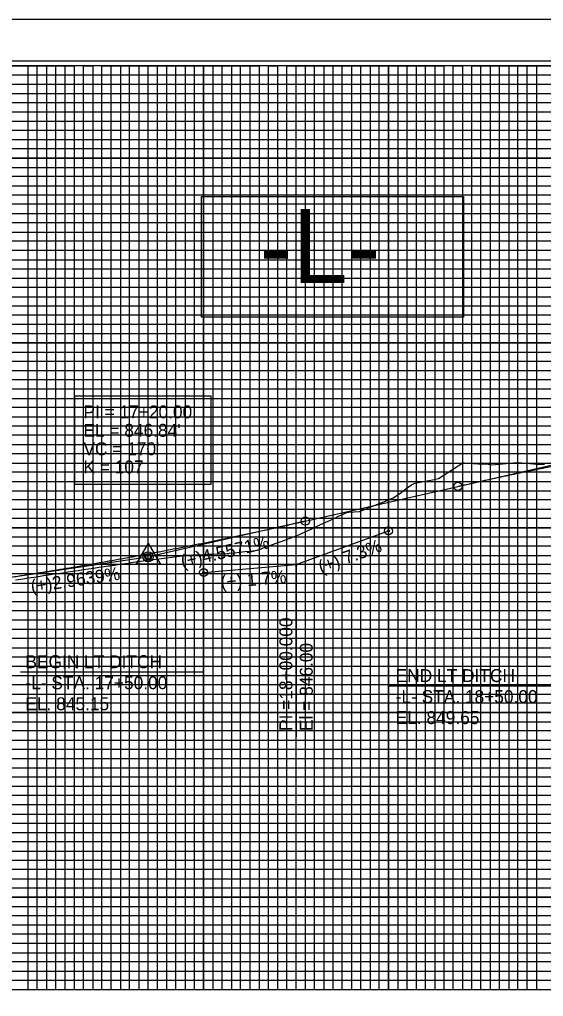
# Model space of a CAD drawing. Extents: x 570622 to 580296, y -55533 to -48575.
# Drawn here: x 571339 to 571622, y -52761 to -52232 of the extents above; entities that cross this region are included whole.
import ezdxf

# ---------------------------------------------------------------- set-up
doc = ezdxf.new("R2010")
doc.units = 0
for name, color, linetype in [('Exist Vertical Profile Ground Line', 7, 'Continuous'), ('Prop Grid Mask', 7, 'Continuous'), ('Prop PFL VPI Symbol CELL', 7, 'Continuous'), ('Prop Vertical Profile Curve Label', 7, 'Continuous'), ('Prop Vertical Profile Ditch Grade Left', 7, 'Continuous'), ('Prop Vertical Profile Ditch Grade Left Label', 7, 'Continuous'), ('Prop Vertical Profile Grade', 7, 'Continuous'), ('Prop Vertical Profile Grade Label', 7, 'Continuous'), ('Prop VPI Ditch Grade Left Label', 7, 'Continuous'), ('Prop VPI Label', 7, 'Continuous'), ('Sheet Cutting Line CELL', 7, 'Continuous'), ('Sheet Data Field CELL', 7, 'Continuous'), ('Sheet DOT Grid CELL', 7, 'Continuous'), ('Sheet Layout Profile Border Port 1', 7, 'Continuous'), ('Sheet Plot Border Inside CELL', 7, 'Continuous'), ('Sheet Plot Border Outside CELL', 7, 'Continuous'), ('Sheet Profile CELL', 7, 'Continuous'), ('Sheet Profile Grid Major CELL', 7, 'Continuous'), ('Sheet Profile Grid Middle CELL', 7, 'Continuous'), ('Sheet Profile Grid Minor CELL', 7, 'Continuous')]:
    doc.layers.add(name, color=color, linetype=linetype)

msp = doc.modelspace()

# ---------------------------------------------------------------- linework, layer by layer
at = {"layer": 'Exist Vertical Profile Ground Line'}
for points in [[(571384.91, -52528.05), (571386.95, -52527.76), (571387.73, -52527.65), (571390.54, -52527.24), (571393.36, -52526.84), (571396.18, -52526.44), (571399, -52526.04), (571399.51, -52525.96), (571401.81, -52525.61), (571404.63, -52525.18), (571407.45, -52524.76), (571407.98, -52524.68), (571410.26, -52524.4), (571413.08, -52524.05), (571415.9, -52523.71), (571417.33, -52523.54), (571418.72, -52523.36), (571421.53, -52522.99), (571423.97, -52522.67), (571424.35, -52522.62), (571427.17, -52522.22), (571428.89, -52521.98), (571429.98, -52521.93), (571432.8, -52521.79), (571435.62, -52521.67), (571438.44, -52521.55), (571441.25, -52521.44), (571444.07, -52521.33), (571446.89, -52521.24), (571449.7, -52521.15), (571450.1, -52521.14), (571452.52, -52520.88), (571455.34, -52520.59), (571458.16, -52520.3), (571460.97, -52520.02), (571463.79, -52519.75), (571466.76, -52519.47), (571469.96, -52518.48), (571470.26, -52518.33), (571470.96, -52517.96), (571472.24, -52517.51), (571475.06, -52516.5), (571477.88, -52515.47), (571480.69, -52514.44), (571483.51, -52513.39), (571486.33, -52512.33), (571489.14, -52511.25), (571490.61, -52510.69), (571491.96, -52510.06), (571494.78, -52508.74), (571497.59, -52507.4), (571500.41, -52506.06), (571501.88, -52505.35), (571503.23, -52504.75), (571506.05, -52503.48), (571508.86, -52502.2), (571511.68, -52500.9), (571514.5, -52499.59), (571516.51, -52498.65), (571517.31, -52498.61), (571520.13, -52498.47), (571522.95, -52498.22), (571525.77, -52497.12), (571528.58, -52496), (571531.4, -52494.88), (571534.22, -52493.74), (571534.68, -52493.55), (571537.03, -52492.62), (571539.85, -52491.5), (571541.25, -52490.94), (571542.67, -52489.94), (571545.49, -52487.94), (571548.3, -52485.92), (571551.12, -52483.9), (571551.8, -52483.41), (571552.83, -52483), (571553.94, -52482.79), (571556.75, -52482.23), (571559.57, -52481.66), (571562.39, -52481.08), (571565.74, -52480.38), (571578.88, -52472), (571579.51, -52471.94), (571589.38, -52472.75), (571591.66, -52472.55), (571594.6, -52473.06), (571608.31, -52471.84), (571608.71, -52471.82), (571621.35, -52472.8), (571622.98, -52472.61)], [(571337.02, -52535.3), (571339.84, -52534.87), (571342.21, -52534.51), (571342.65, -52534.44), (571345.47, -52534), (571348.29, -52533.57), (571351.11, -52533.13), (571352.05, -52532.99), (571353.92, -52532.7), (571356.74, -52532.27), (571359.56, -52531.85), (571362.37, -52531.42), (571364.6, -52531.08), (571365.19, -52530.99), (571368.01, -52530.57), (571370.83, -52530.14), (571373.64, -52529.72), (571376.46, -52529.3), (571379.28, -52528.88), (571382.09, -52528.47), (571383.66, -52528.24), (571384.91, -52528.05)]]:
    msp.add_lwpolyline(points, dxfattribs=at)
at = {"layer": 'Prop Grid Mask'}
for points in [[(571437.59, -52327.87), (571579.27, -52327.87), (571579.27, -52393.13), (571437.59, -52393.13)], [(571369.03, -52435.65), (571442.68, -52435.65), (571442.68, -52483.76), (571369.03, -52483.76)]]:
    msp.add_lwpolyline(points, close=True, dxfattribs=at)
at = {"layer": 'Prop PFL VPI Symbol CELL'}
for p, q in [((571408.68, -52515.37), (571402.23, -52526.57)), ((571408.68, -52515.37), (571415.18, -52526.57)), ((571402.23, -52526.57), (571415.18, -52526.57))]:
    msp.add_line(p, q, dxfattribs=at)
for radius in [1.75, 1.2]:
    msp.add_circle((571408.69, -52522.85), radius, dxfattribs=at)
at = {"layer": 'Prop Vertical Profile Curve Label'}
for centre in [(571576.19, -52484.69), (571493.69, -52503.49)]:
    msp.add_circle(centre, 2.25, dxfattribs=at)
at = {"layer": 'Prop Vertical Profile Ditch Grade Left'}
msp.add_lwpolyline([(571438.69, -52531.3), (571488.69, -52527.05), (571538.69, -52508.8)], dxfattribs=at)
at = {"layer": 'Prop Vertical Profile Ditch Grade Left Label'}
for p, q in [((571538.69, -52508.8), (571538.69, -52592.8)), ((571488.69, -52527.05), (571488.69, -52620.19)), ((571438.69, -52531.3), (571438.69, -52585.3)), ((571438.69, -52585.3), (571339.59, -52585.3)), ((571637.94, -52592.8), (571538.69, -52592.8))]:
    msp.add_line(p, q, dxfattribs=at)
at = {"layer": 'Prop Vertical Profile Grade'}
msp.add_line((571493.69, -52503.49), (571576.19, -52484.69), dxfattribs=at)
for points in [[(571576.19, -52484.69), (571580.69, -52483.67), (571585.19, -52482.66), (571589.69, -52481.66), (571594.19, -52480.67), (571598.69, -52479.7), (571603.19, -52478.73), (571607.69, -52477.78), (571612.19, -52476.83), (571616.69, -52475.9), (571621.19, -52474.98), (571625.69, -52474.07), (571630.19, -52473.17), (571634.69, -52472.28), (571639.19, -52471.4), (571643.69, -52470.54), (571648.19, -52469.68), (571652.69, -52468.84), (571657.19, -52468), (571661.69, -52467.18), (571666.19, -52466.37), (571670.69, -52465.56), (571675.19, -52464.77), (571679.69, -52463.99), (571684.19, -52463.22), (571688.69, -52462.47), (571693.19, -52461.72), (571697.69, -52460.98), (571702.19, -52460.26), (571706.69, -52459.54), (571711.19, -52458.84), (571715.69, -52458.15), (571720.19, -52457.47), (571724.69, -52456.8), (571729.19, -52456.14), (571733.69, -52455.49), (571738.19, -52454.85), (571742.69, -52454.22), (571747.19, -52453.61), (571751.69, -52453), (571756.19, -52452.41), (571760.69, -52451.83), (571765.19, -52451.25), (571769.69, -52450.69), (571774.19, -52450.14), (571778.69, -52449.6), (571783.19, -52449.07), (571787.69, -52448.56), (571792.19, -52448.05), (571796.69, -52447.55), (571801.19, -52447.07)], [(571323.69, -52535.45), (571327.09, -52534.94), (571330.49, -52534.43), (571333.89, -52533.92), (571337.29, -52533.39), (571340.69, -52532.86), (571344.09, -52532.33), (571347.49, -52531.79), (571350.89, -52531.25), (571354.29, -52530.7), (571357.69, -52530.14), (571361.09, -52529.58), (571364.49, -52529.01), (571367.89, -52528.44), (571371.29, -52527.87), (571374.69, -52527.28), (571378.09, -52526.7), (571381.49, -52526.1), (571384.89, -52525.5), (571388.29, -52524.9), (571391.69, -52524.29), (571395.09, -52523.68), (571398.49, -52523.06), (571401.89, -52522.43), (571405.29, -52521.8), (571408.69, -52521.16), (571412.09, -52520.52), (571415.49, -52519.87), (571418.89, -52519.22), (571422.29, -52518.56), (571425.69, -52517.9), (571429.09, -52517.23), (571432.49, -52516.55), (571435.89, -52515.87), (571439.29, -52515.19), (571442.69, -52514.5), (571446.09, -52513.8), (571449.49, -52513.1), (571452.89, -52512.39), (571456.29, -52511.68), (571459.69, -52510.96), (571463.09, -52510.24), (571466.49, -52509.51), (571469.89, -52508.78), (571473.29, -52508.04), (571476.69, -52507.29), (571480.09, -52506.54), (571483.49, -52505.79), (571486.89, -52505.03), (571490.29, -52504.26), (571493.69, -52503.49)]]:
    msp.add_spline(points, degree=3, dxfattribs=at)
at = {"layer": 'Prop VPI Ditch Grade Left Label'}
for centre, radius in [((571538.69, -52508.8), 2.14), ((571538.69, -52508.8), 0.5), ((571438.69, -52531.3), 2.14), ((571488.69, -52527.05), 0.5), ((571438.69, -52531.3), 0.5)]:
    msp.add_circle(centre, radius, dxfattribs=at)
at = {"layer": 'Prop VPI Label'}
for p, q in [((571576.19, -52484.69), (571686.01, -52459.67)), ((571493.69, -52503.49), (571411.37, -52522.24)), ((571323.69, -52535.45), (571405.97, -52523.26))]:
    msp.add_line(p, q, dxfattribs=at)
msp.add_circle((571408.69, -52522.85), 2.75, dxfattribs=at)
at = {"layer": 'Sheet Cutting Line CELL'}
msp.add_line((572305.69, -52232.05), (570621.69, -52232.05), dxfattribs=at)
at = {"layer": 'Sheet DOT Grid CELL'}
for p, q in [((571388.69, -52757.05), (571388.69, -52257.05)), ((571438.69, -52757.05), (571438.69, -52257.05)), ((571488.69, -52757.05), (571488.69, -52257.05)), ((571538.69, -52757.05), (571538.69, -52257.05)), ((571588.69, -52757.05), (571588.69, -52257.05)), ((572088.64, -52307.05), (570788.69, -52307.05)), ((572088.64, -52357.05), (570788.69, -52357.05)), ((572288.69, -52407.05), (570788.69, -52407.05)), ((572288.69, -52457.05), (570788.69, -52457.05)), ((572288.69, -52507.05), (570788.69, -52507.05)), ((572288.69, -52557.05), (570788.69, -52557.05)), ((572288.69, -52607.05), (570788.69, -52607.05)), ((572288.69, -52657.05), (570788.69, -52657.05)), ((572288.69, -52707.05), (570788.69, -52707.05))]:
    msp.add_line(p, q, dxfattribs=at)
at = {"layer": 'Sheet Layout Profile Border Port 1'}
msp.add_lwpolyline([(570838.69, -52257.05), (570838.69, -52757.05), (572238.69, -52757.05), (572238.69, -52394.6), (572088.64, -52394.6), (572088.64, -52257.05)], close=True, dxfattribs=at)
at = {"layer": 'Sheet Plot Border Inside CELL'}
msp.add_lwpolyline([(570634.69, -53309.6), (572301.19, -53309.6), (572301.19, -52254.5), (570634.69, -52254.5)], close=True, dxfattribs=at)
at = {"layer": 'Sheet Plot Border Outside CELL'}
msp.add_lwpolyline([(570621.69, -53332.05), (572305.69, -53332.05), (572305.69, -52232.05), (570621.69, -52232.05)], close=True, dxfattribs=at)
at = {"layer": 'Sheet Profile CELL'}
msp.add_line((570788.69, -52757.05), (572288.69, -52757.05), dxfattribs=at)
msp.add_lwpolyline([(572288.69, -52257.05), (570788.69, -52257.05), (570788.69, -53307.05), (572288.69, -53307.05)], close=True, dxfattribs=at)
at = {"layer": 'Sheet Profile Grid Major CELL'}
for points in [[(571338.69, -52757.05), (571388.69, -52757.05), (571388.69, -52257.05), (571438.69, -52257.05), (571438.69, -52757.05), (571488.69, -52757.05), (571488.69, -52257.05), (571538.69, -52257.05), (571538.69, -52757.05), (571588.69, -52757.05), (571588.69, -52257.05), (571638.69, -52257.05), (571638.69, -52757.05), (571688.69, -52757.05), (571688.69, -52257.05), (571738.69, -52257.05), (571738.69, -52757.05), (571788.69, -52757.05), (571788.69, -52257.05), (571838.69, -52257.05), (571838.69, -52757.05), (571888.69, -52757.05)], [(570788.69, -52307.05), (572088.69, -52307.05)], [(572088.69, -52357.05), (570788.69, -52357.05), (570788.69, -52407.05), (572288.69, -52407.05)], [(572288.69, -52457.05), (570788.69, -52457.05), (570788.69, -52507.05), (572288.69, -52507.05)], [(572288.69, -52557.05), (570788.69, -52557.05), (570788.69, -52607.05), (572288.69, -52607.05)], [(572288.69, -52657.05), (570788.69, -52657.05), (570788.69, -52657.05), (570788.69, -52707.05), (572288.69, -52707.05)]]:
    msp.add_lwpolyline(points, dxfattribs=at)
at = {"layer": 'Sheet Profile Grid Middle CELL'}
msp.add_line((570788.69, -52282.05), (572088.64, -52282.05), dxfattribs=at)
for points in [[(571313.69, -52257.05), (571363.69, -52257.05), (571363.69, -52757.05), (571413.69, -52757.05), (571413.69, -52757.05), (571413.69, -52257.05), (571463.69, -52257.05), (571463.69, -52757.05), (571513.69, -52757.05), (571513.69, -52257.05), (571563.69, -52257.05), (571563.69, -52757.05), (571613.69, -52757.05), (571613.69, -52257.05), (571663.69, -52257.05)], [(572088.69, -52332.05), (570788.69, -52332.05), (570788.69, -52382.05), (572088.69, -52382.05)], [(572288.69, -52432.05), (570788.69, -52432.05), (570788.69, -52482.05), (572113.69, -52482.05)], [(572288.69, -52532.05), (570788.69, -52532.05), (570788.69, -52582.05), (572288.69, -52582.05)], [(572288.69, -52632.05), (570788.69, -52632.05), (570788.69, -52682.05), (572288.69, -52682.05)], [(572288.69, -52732.05), (570788.69, -52732.05)]]:
    msp.add_lwpolyline(points, dxfattribs=at)
at = {"layer": 'Sheet Profile Grid Minor CELL'}
for p, q in [((570838.69, -52262.05), (572088.69, -52262.05)), ((572088.69, -52267.05), (570838.69, -52267.4)), ((570838.69, -52272.05), (572088.69, -52272.05)), ((572088.64, -52392.05), (570838.69, -52392.05)), ((572238.69, -52397.05), (570838.69, -52397.05)), ((572238.69, -52402.05), (570838.69, -52402.05)), ((570838.69, -52412.05), (572238.69, -52412.05)), ((572238.69, -52417.05), (570838.69, -52417.05)), ((570838.69, -52422.05), (572238.69, -52422.05)), ((572238.69, -52442.05), (570838.69, -52442.05)), ((570838.69, -52447.05), (572238.69, -52447.05)), ((572238.69, -52467.05), (570838.69, -52467.05)), ((570838.69, -52472.05), (572238.69, -52472.05)), ((572238.69, -52492.05), (570838.69, -52492.05)), ((570838.69, -52497.05), (572238.69, -52497.05)), ((572238.69, -52502.05), (570838.69, -52502.05)), ((570838.69, -52512.05), (572238.69, -52512.05)), ((572238.69, -52517.05), (570838.69, -52517.05)), ((570838.69, -52522.05), (572238.69, -52522.05)), ((572238.69, -52527.05), (570838.69, -52527.05)), ((570838.69, -52537.05), (572238.69, -52537.05)), ((572238.69, -52542.05), (570838.69, -52542.05)), ((570838.69, -52547.05), (572238.69, -52547.05)), ((572238.69, -52552.05), (570838.69, -52552.05)), ((570838.69, -52562.05), (572238.69, -52562.05)), ((572238.69, -52567.05), (570838.69, -52567.05)), ((570838.69, -52572.05), (572238.69, -52572.05)), ((572238.69, -52577.05), (570838.69, -52577.05)), ((570838.69, -52587.05), (572238.69, -52587.05)), ((572238.69, -52592.05), (570838.69, -52592.05)), ((570838.69, -52597.05), (572238.69, -52597.05)), ((572238.69, -52602.05), (570838.69, -52602.05)), ((570838.69, -52612.05), (572238.69, -52612.05)), ((572238.69, -52617.05), (570838.69, -52617.05)), ((570838.69, -52622.05), (572238.69, -52622.05)), ((572238.69, -52627.05), (570838.69, -52627.05)), ((570838.69, -52637.05), (572238.69, -52637.05)), ((572238.69, -52642.05), (570838.69, -52642.05)), ((572238.69, -52647.05), (570838.69, -52647.05)), ((572238.69, -52652.05), (570838.69, -52652.05)), ((570838.69, -52662.05), (572238.69, -52662.05)), ((572238.69, -52667.05), (570838.69, -52667.05)), ((570838.69, -52672.05), (572238.69, -52672.05)), ((572238.69, -52677.05), (570838.69, -52677.05)), ((570838.69, -52687.05), (572238.69, -52687.05)), ((572238.69, -52692.05), (570838.69, -52692.05)), ((570838.69, -52697.05), (572238.69, -52697.05)), ((572238.69, -52702.05), (570838.69, -52702.05)), ((570838.69, -52712.05), (572238.69, -52712.05)), ((572238.69, -52717.05), (570838.69, -52717.05)), ((570838.69, -52722.05), (572238.69, -52722.05)), ((572238.69, -52727.05), (570838.69, -52727.05)), ((570838.69, -52737.05), (572238.69, -52737.05)), ((572238.69, -52742.05), (570838.69, -52742.05)), ((570838.69, -52747.05), (572238.69, -52747.05))]:
    msp.add_line(p, q, dxfattribs=at)
for points in [[(571333.69, -52257.05), (571343.69, -52257.05), (571343.69, -52757.05), (571348.69, -52757.05), (571348.69, -52257.05), (571353.69, -52257.05), (571353.69, -52757.05), (571358.69, -52757.05), (571358.69, -52257.05), (571368.69, -52257.05)], [(571368.69, -52257.05), (571368.69, -52757.05), (571373.69, -52757.05), (571373.69, -52257.05), (571378.69, -52257.05), (571378.69, -52757.05), (571383.69, -52757.05), (571383.69, -52257.05), (571393.69, -52257.05), (571393.69, -52757.05), (571398.69, -52757.05), (571398.69, -52257.05), (571403.69, -52257.05), (571403.69, -52757.05), (571408.69, -52757.05), (571408.69, -52257.05), (571418.69, -52257.05), (571418.69, -52757.05), (571423.69, -52757.05), (571423.69, -52257.05), (571428.69, -52257.05), (571428.69, -52757.05), (571433.69, -52757.05), (571433.69, -52257.05), (571443.69, -52257.05), (571443.69, -52757.05), (571448.69, -52757.05), (571448.69, -52257.05), (571453.69, -52257.05), (571453.69, -52757.05), (571458.69, -52757.05), (571458.69, -52257.05), (571468.69, -52257.05), (571468.69, -52757.05), (571473.69, -52757.05), (571473.69, -52257.05), (571478.69, -52257.05), (571478.69, -52757.05), (571483.69, -52757.05), (571483.69, -52257.05), (571493.69, -52257.05), (571493.69, -52757.05), (571493.69, -52757.05), (571498.69, -52757.05), (571498.69, -52257.05), (571503.69, -52257.05), (571503.69, -52757.05), (571508.69, -52757.05), (571508.69, -52257.05), (571518.69, -52257.05), (571518.69, -52757.05), (571523.69, -52757.05), (571523.69, -52257.05), (571528.69, -52257.05), (571528.69, -52757.05), (571533.69, -52757.05), (571533.69, -52257.05), (571543.69, -52257.05), (571543.69, -52757.05), (571548.69, -52757.05), (571548.69, -52257.05), (571553.69, -52257.05), (571553.69, -52757.05), (571558.69, -52757.05), (571558.69, -52257.05), (571568.69, -52257.05), (571568.69, -52757.05), (571573.69, -52757.05), (571573.69, -52257.05), (571578.69, -52257.05), (571578.69, -52757.05), (571583.69, -52757.05), (571583.69, -52257.05), (571593.69, -52257.05), (571593.69, -52757.05), (571598.69, -52757.05), (571598.69, -52257.05), (571603.69, -52257.05), (571603.69, -52757.05), (571608.69, -52757.05), (571608.69, -52257.05), (571618.69, -52257.05), (571618.69, -52757.05), (571623.69, -52757.05)], [(572088.69, -52277.05), (570838.69, -52277.05), (570838.69, -52287.05), (572088.69, -52287.05)], [(572088.64, -52292.05), (570838.69, -52292.05), (570838.69, -52297.05), (572088.69, -52297.05)], [(572088.69, -52302.05), (570838.69, -52302.05), (570838.69, -52312.05), (572088.69, -52312.05)], [(572088.69, -52317.05), (570838.69, -52317.05), (570838.69, -52322.05), (572088.69, -52322.05)], [(572088.69, -52327.05), (570838.69, -52327.05), (570838.69, -52337.05), (572088.69, -52337.05)], [(572088.69, -52342.05), (570838.69, -52342.05), (570838.69, -52347.05), (572088.69, -52347.05)], [(572088.69, -52352.05), (570838.69, -52352.05), (570838.69, -52362.05), (572088.69, -52362.05)], [(572088.69, -52367.15), (570838.79, -52367.15), (570838.79, -52372.05), (572088.69, -52372.05)], [(572088.69, -52377.05), (570838.69, -52377.05), (570838.69, -52387.05), (572088.69, -52387.05)], [(572238.69, -52427.05), (570838.69, -52427.05), (570838.69, -52437.05), (572238.69, -52437.05)], [(572238.69, -52452.05), (570838.69, -52452.05), (570838.69, -52462.05), (572238.69, -52462.05)], [(572238.69, -52477.05), (570838.69, -52477.05), (570838.69, -52487.05), (572238.69, -52487.05)], [(572238.69, -52752.05), (570838.69, -52752.05)]]:
    msp.add_lwpolyline(points, dxfattribs=at)

# ---------------------------------------------------------------- texts
at = {"layer": 'Prop Vertical Profile Curve Label'}
for s, p in [("VC = 170'", (571373.69, -52467.85)), ('K = 107', (571373.69, -52477.68))]:
    msp.add_text(s, height=7, dxfattribs=at).set_placement(p)
at = {"layer": 'Prop Vertical Profile Ditch Grade Left Label'}
for s, rotation, p in [('(+) 7.3%', 20.0521, (571502.23, -52531.87)), ('(+) 1.7%', 4.8585, (571448.16, -52539.94))]:
    msp.add_text(s, height=7, rotation=rotation, dxfattribs=at).set_placement(p)
at = {"layer": 'Prop Vertical Profile Grade Label'}
for s, rotation, p in [('(+)4.5571%', 12.8361, (571427.23, -52528.88)), ('(+)2.9639%', 8.4296, (571345.73, -52542.29))]:
    msp.add_text(s, height=7, rotation=rotation, dxfattribs=at).set_placement(p)
at = {"layer": 'Prop VPI Ditch Grade Left Label'}
for s, p in [('PI =18+00.000', (571486.69, -52617.05)), ('El = 846.00', (571497.69, -52617.05))]:
    msp.add_text(s, height=7, rotation=90, dxfattribs=at).set_placement(p)
for s, p in [('BEGIN LT DITCH', (571342.31, -52583.08)), ('END LT DITCH', (571542.56, -52590.58)), ('-L- STA. 17+50.00', (571342.31, -52594.46)), ('-L- STA. 18+50.00', (571542.56, -52601.96)), ('EL. 845.15', (571342.31, -52605.83)), ('EL. 849.65', (571542.56, -52613.33))]:
    msp.add_text(s, height=7, dxfattribs=at).set_placement(p)
at = {"layer": 'Prop VPI Label'}
for s, p in [('PI = 17+20.00', (571373.69, -52447.85)), ("EL = 846.84'", (571373.69, -52457.85))]:
    msp.add_text(s, height=7, dxfattribs=at).set_placement(p)
at = {"layer": 'Sheet Data Field CELL'}
msp.add_text('-L-', height=40, dxfattribs=at).set_placement((571468.97, -52374.67))

doc.saveas('drawing.dxf')
